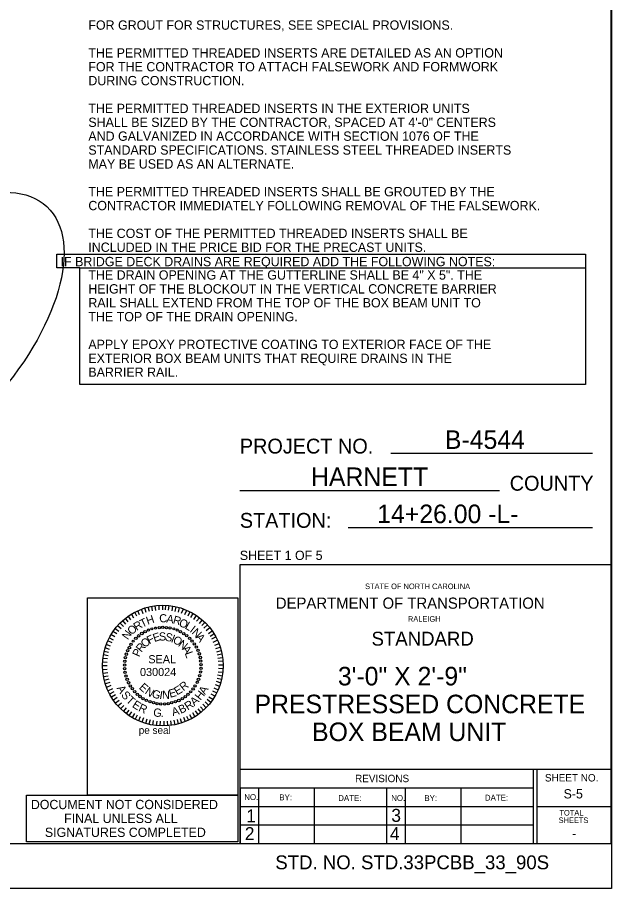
# Model space of a CAD drawing. Extents: x -38 to 94, y -165 to 80.
# Drawn here: x 54.62 to 75.99, y 16.93 to 48.24 of the extents above; entities that cross this region are included whole.
import ezdxf

# ---------------------------------------------------------------- set-up
doc = ezdxf.new("R2010")
doc.units = 0
for name, color, linetype in [('Peseal', 7, 'Continuous'), ('Plan Sheet CELL', 7, 'Continuous'), ('Plot Shape CELL', 7, 'Continuous'), ('Sheet Sticker Exception Certification CELL', 7, 'Continuous'), ('Subtitle Text', 7, 'Continuous'), ('Text', 7, 'Continuous'), ('Title Text', 7, 'Continuous'), ('User Information Notes', 7, 'Continuous'), ('User Information Notes CELL', 7, 'Continuous')]:
    doc.layers.add(name, color=color, linetype=linetype)

msp = doc.modelspace()

# ---------------------------------------------------------------- linework, layer by layer
at = {"layer": 'Peseal'}
for p, q in [((59.14, 26.807), (59.077, 26.964)), ((59.255, 26.849), (59.203, 27.016)), ((59.369, 26.88), (59.328, 27.047)), ((59.484, 26.912), (59.453, 27.079)), ((59.599, 26.922), (59.578, 27.089)), ((59.724, 26.943), (59.714, 27.11)), ((59.849, 26.943), (59.849, 27.11)), ((59.943, 26.943), (59.953, 27.11)), ((60.058, 26.933), (60.079, 27.099)), ((60.183, 26.912), (60.204, 27.079)), ((60.298, 26.891), (60.329, 27.058)), ((60.412, 26.86), (60.454, 27.026)), ((60.527, 26.828), (60.59, 26.985)), ((60.642, 26.776), (60.715, 26.933)), ((58.608, 26.515), (58.504, 26.64)), ((58.702, 26.588), (58.608, 26.724)), ((58.806, 26.651), (58.723, 26.797)), ((58.91, 26.713), (58.837, 26.86)), ((59.015, 26.766), (58.952, 26.912)), ((60.757, 26.724), (60.83, 26.88)), ((60.861, 26.672), (60.944, 26.818)), ((60.965, 26.599), (61.059, 26.745)), ((61.059, 26.536), (61.163, 26.661)), ((58.347, 26.265), (58.222, 26.369)), ((58.431, 26.348), (58.306, 26.474)), ((58.514, 26.432), (58.41, 26.557)), ((61.163, 26.453), (61.268, 26.578)), ((61.247, 26.38), (61.361, 26.494)), ((61.33, 26.286), (61.455, 26.401)), ((61.403, 26.202), (61.539, 26.307)), ((58.128, 25.973), (57.982, 26.056)), ((58.201, 26.077), (58.055, 26.171)), ((58.264, 26.171), (58.139, 26.265)), ((61.487, 26.098), (61.622, 26.192)), ((61.549, 26.004), (61.685, 26.088)), ((57.972, 25.639), (57.815, 25.702)), ((58.024, 25.754), (57.868, 25.827)), ((58.076, 25.858), (57.92, 25.942)), ((61.612, 25.9), (61.758, 25.973)), ((61.664, 25.785), (61.81, 25.858)), ((61.716, 25.671), (61.873, 25.733)), ((57.899, 25.41), (57.742, 25.451)), ((57.93, 25.524), (57.774, 25.577)), ((61.758, 25.556), (61.914, 25.608)), ((61.789, 25.441), (61.946, 25.483)), ((57.847, 25.055), (57.68, 25.066)), ((57.857, 25.18), (57.701, 25.201)), ((57.878, 25.295), (57.711, 25.326)), ((61.81, 25.326), (61.977, 25.358)), ((61.831, 25.212), (61.998, 25.232)), ((61.841, 25.097), (62.008, 25.107)), ((57.847, 24.93), (57.68, 24.93)), ((57.847, 24.805), (57.68, 24.794)), ((61.852, 24.972), (62.019, 24.972)), ((61.852, 24.847), (62.019, 24.836)), ((57.868, 24.68), (57.701, 24.659)), ((57.878, 24.565), (57.721, 24.534)), ((57.909, 24.45), (57.742, 24.409)), ((61.8, 24.492), (61.966, 24.45)), ((61.82, 24.607), (61.987, 24.575)), ((61.841, 24.721), (62.008, 24.701)), ((57.941, 24.336), (57.784, 24.283)), ((57.982, 24.221), (57.826, 24.158)), ((61.685, 24.137), (61.841, 24.075)), ((61.737, 24.263), (61.893, 24.2)), ((61.768, 24.377), (61.935, 24.325)), ((58.034, 24.106), (57.878, 24.033)), ((58.087, 24.002), (57.93, 23.918)), ((58.149, 23.887), (58.003, 23.804)), ((61.507, 23.824), (61.654, 23.731)), ((61.58, 23.929), (61.727, 23.845)), ((61.633, 24.033), (61.789, 23.96)), ((58.212, 23.793), (58.076, 23.699)), ((58.285, 23.689), (58.149, 23.585)), ((58.358, 23.595), (58.243, 23.491)), ((58.452, 23.512), (58.326, 23.386)), ((61.288, 23.553), (61.414, 23.428)), ((61.372, 23.637), (61.497, 23.522)), ((61.445, 23.731), (61.58, 23.626)), ((58.535, 23.428), (58.431, 23.303)), ((58.629, 23.345), (58.535, 23.22)), ((58.723, 23.282), (58.629, 23.147)), ((58.827, 23.22), (58.744, 23.074)), ((60.809, 23.188), (60.892, 23.032)), ((60.913, 23.251), (61.007, 23.105)), ((61.017, 23.313), (61.111, 23.178)), ((61.111, 23.386), (61.215, 23.251)), ((61.205, 23.459), (61.309, 23.345)), ((58.931, 23.157), (58.858, 23.011)), ((59.036, 23.105), (58.973, 22.959)), ((59.15, 23.063), (59.098, 22.907)), ((59.276, 23.021), (59.223, 22.865)), ((59.39, 22.99), (59.349, 22.834)), ((59.505, 22.969), (59.474, 22.802)), ((59.63, 22.948), (59.609, 22.781)), ((59.755, 22.938), (59.745, 22.771)), ((59.88, 22.938), (59.88, 22.771)), ((60.006, 22.948), (60.016, 22.781)), ((60.131, 22.959), (60.152, 22.792)), ((60.245, 22.98), (60.277, 22.813)), ((60.36, 23), (60.402, 22.844)), ((60.475, 23.042), (60.527, 22.875)), ((60.59, 23.084), (60.652, 22.927)), ((60.704, 23.126), (60.777, 22.98))]:
    msp.add_line(p, q, dxfattribs=at)
for centre, radius in [((59.583, 26.291), 0.0369), ((59.719, 26.307), 0.042), ((59.849, 26.317), 0.0417), ((59.98, 26.307), 0.042), ((60.11, 26.296), 0.043), ((58.978, 26.009), 0.0449), ((59.093, 26.093), 0.0449), ((59.213, 26.161), 0.0466), ((59.333, 26.218), 0.0397), ((59.453, 26.26), 0.038), ((60.245, 26.26), 0.038), ((60.365, 26.218), 0.0397), ((60.485, 26.155), 0.042), ((60.6, 26.093), 0.042), ((60.71, 26.015), 0.0407), ((58.707, 25.707), 0.0449), ((58.78, 25.822), 0.0369), ((58.879, 25.921), 0.0442), ((60.814, 25.921), 0.0407), ((60.903, 25.822), 0.0407), ((60.981, 25.723), 0.042), ((58.535, 25.352), 0.0446), ((58.582, 25.478), 0.0397), ((58.645, 25.587), 0.0481), ((61.054, 25.608), 0.042), ((61.116, 25.488), 0.0397), ((61.163, 25.363), 0.0446), ((58.483, 25.092), 0.042), ((58.504, 25.222), 0.043), ((61.195, 25.232), 0.043), ((61.215, 25.102), 0.042), ((58.472, 24.831), 0.042), ((58.472, 24.961), 0.0417), ((58.493, 24.695), 0.042), ((61.205, 24.706), 0.042), ((61.226, 24.972), 0.0417), ((61.226, 24.841), 0.042), ((58.525, 24.565), 0.043), ((58.566, 24.445), 0.0446), ((61.132, 24.445), 0.0446), ((61.174, 24.575), 0.043), ((58.618, 24.325), 0.0466), ((58.676, 24.21), 0.042), ((58.754, 24.111), 0.0407), ((60.939, 24.101), 0.0449), ((61.012, 24.21), 0.042), ((61.085, 24.336), 0.042), ((58.837, 24.002), 0.0442), ((58.931, 23.908), 0.0442), ((59.03, 23.83), 0.0449), ((59.14, 23.757), 0.042), ((60.548, 23.757), 0.042), ((60.657, 23.824), 0.0407), ((60.751, 23.908), 0.0407), ((60.85, 23.997), 0.0407), ((59.26, 23.694), 0.0397), ((59.385, 23.647), 0.0446), ((59.515, 23.605), 0.043), ((59.646, 23.574), 0.042), ((59.776, 23.564), 0.0417), ((59.912, 23.564), 0.0417), ((60.042, 23.574), 0.042), ((60.172, 23.605), 0.043), ((60.303, 23.642), 0.0397), ((60.423, 23.689), 0.0466)]:
    msp.add_circle(centre, radius, dxfattribs=at)
at = {"layer": 'Plan Sheet CELL'}
for p, q in [((75.969, 74.615), (75.969, 18.545)), ((75.302, 32.563), (68.047, 32.563)), ((71.964, 31.228), (62.619, 31.228)), ((75.302, 29.894), (66.518, 29.894)), ((75.969, 28.558), (62.619, 28.558)), ((62.619, 28.558), (62.619, 18.545)), ((62.619, 21.216), (75.969, 21.216)), ((73.166, 21.216), (73.166, 18.545)), ((73.3, 21.216), (73.3, 18.545)), ((62.619, 20.549), (73.171, 20.549)), ((62.628, 20.549), (62.628, 18.545)), ((63.286, 20.549), (63.286, 18.545)), ((65.288, 20.537), (65.288, 18.535)), ((67.894, 20.549), (67.894, 18.528)), ((68.563, 20.549), (68.563, 18.543)), ((70.565, 20.549), (70.565, 18.543)), ((62.619, 19.88), (73.193, 19.88)), ((73.3, 19.88), (75.946, 19.88)), ((62.619, 19.213), (73.171, 19.213)), ((-9.472, 18.545), (75.969, 18.545)), ((75.992, 16.927), (75.992, 16.927))]:
    msp.add_line(p, q, dxfattribs=at)
at = {"layer": 'Plot Shape CELL'}
msp.add_lwpolyline([(-12.286, 75.667), (75.992, 75.667), (75.992, 16.927), (-12.286, 16.927)], close=True, dxfattribs=at)
at = {"layer": 'Sheet Sticker Exception Certification CELL'}
msp.add_lwpolyline([(54.947, 20.286), (62.553, 20.286), (62.553, 18.612), (54.947, 18.612)], close=True, dxfattribs=at)
at = {"layer": 'User Information Notes'}
for p, q in [((56.862, 39.237), (75.059, 39.237)), ((59.849, 24.94), (59.849, 24.94))]:
    msp.add_line(p, q, dxfattribs=at)
msp.add_lwpolyline([(56.862, 39.237), (56.041, 39.237), (56.041, 39.735), (75.059, 39.735), (75.059, 35.039), (56.862, 35.039)], close=True, dxfattribs=at)
msp.add_ellipse((51.167, 36.612), major_axis=(4.509, 4.826), ratio=0.506929, dxfattribs=at)
at = {"layer": 'User Information Notes CELL'}
msp.add_line((59.849, 24.94), (59.849, 24.94), dxfattribs=at)
msp.add_lwpolyline([(57.146, 27.377), (62.553, 27.377), (62.553, 20.286), (57.146, 20.286)], close=True, dxfattribs=at)
msp.add_circle((59.849, 24.94), 2.169, dxfattribs=at)

# ---------------------------------------------------------------- texts
at = {"layer": 'Peseal'}
for s, height, rotation, p in [('T', 0.292, 25.943, (59.109, 26.296)), ('H', 0.292, 18.9162, (59.307, 26.401)), ('C', 0.292, 4.8625, (59.734, 26.484)), ('A', 0.292, 350.8088, (59.964, 26.494)), ('R', 0.292, 343.7819, (60.193, 26.463)), ('O', 0.292, 336.7551, (60.402, 26.38)), ('O', 0.292, 39.9967, (58.723, 26.025)), ('R', 0.292, 32.9699, (58.91, 26.182)), ('L', 0.292, 329.7282, (60.621, 26.286)), ('I', 0.292, 322.7014, (60.798, 26.171)), ('N', 0.292, 54.0504, (58.587, 25.848)), ('F', 0.292, 26.4777, (59.359, 25.702)), ('E', 0.292, 18.4448, (59.547, 25.785)), ('S', 0.292, 2.3789, (59.714, 25.837)), ('S', 0.292, 346.313, (59.912, 25.848)), ('I', 0.292, 338.28, (60.12, 25.796)), ('O', 0.292, 330.2471, (60.183, 25.785)), ('N', 0.292, 315.6745, (60.871, 26.109)), ('A', 0.292, 308.6477, (61.017, 25.952)), ('R', 0.292, 50.5765, (59.077, 25.399)), ('O', 0.292, 42.5436, (59.213, 25.566)), ('N', 0.292, 322.2141, (60.381, 25.66)), ('P', 0.292, 66.6424, (59.004, 25.232)), ('A', 0.292, 306.1483, (60.527, 25.535)), ('L', 0.292, 290.0824, (60.631, 25.389)), ('A', 0.296, 300.3993, (58.181, 24.131)), ('E', 0.292, 318.5179, (58.973, 24.127)), ('N', 0.292, 326.5361, (59.182, 23.95)), ('E', 0.292, 14.6452, (60.11, 23.783)), ('E', 0.292, 30.6815, (60.36, 23.866)), ('R', 0.292, 38.6997, (60.59, 24.012)), ('A', 0.296, 59.6007, (61.37, 23.879)), ('S', 0.296, 309.4349, (58.329, 23.879)), ('T', 0.296, 318.1096, (58.506, 23.662)), ('G', 0.292, 342.5725, (59.432, 23.814)), ('I', 0.292, 350.5906, (59.714, 23.751)), ('N', 0.292, 358.6088, (59.818, 23.751)), ('A', 0.296, 42.3241, (60.986, 23.476)), ('H', 0.296, 51.3597, (61.202, 23.672)), ('E', 0.296, 327.1453, (58.724, 23.467)), ('R', 0.296, 335.458, (58.949, 23.32)), ('B', 0.296, 24.8312, (60.493, 23.202)), ('R', 0.296, 33.5776, (60.75, 23.32)), ('G', 0.296, 353.3858, (59.491, 23.121)), ('A', 0.296, 15.7955, (60.212, 23.122)), ('.', 0.296, 2.1323, (59.772, 23.088))]:
    msp.add_text(s, height=height, rotation=rotation, dxfattribs=at).set_placement(p)
for s, p in [('SEAL', (59.328, 25.024)), ('030024', (59.028, 24.565))]:
    msp.add_text(s, height=0.2921, dxfattribs=at).set_placement(p)
at = {"layer": 'Plan Sheet CELL'}
for s, height, p in [('PROJECT NO.', 0.534, (62.619, 32.563)), ('COUNTY', 0.534, (72.328, 31.228)), ('STATION:', 0.534, (62.619, 29.894)), ('SHEET 1 OF 5 ', 0.33375, (62.619, 28.737)), ('STATE OF NORTH CAROLINA', 0.20024, (67.124, 27.69)), ('DEPARTMENT OF TRANSPORTATION', 0.40049, (63.914, 26.986)), ('RALEIGH', 0.2002, (68.666, 26.518)), ('REVISIONS', 0.267, (66.765, 20.751)), ('SHEET NO.', 0.267, (73.594, 20.776)), ('NO.', 0.2128, (62.778, 20.109)), ('BY:', 0.2128, (64.038, 20.099)), ('DATE:', 0.2128, (66.159, 20.075)), ('NO.', 0.2128, (68.064, 20.075)), ('BY:', 0.2128, (69.257, 20.074)), ('DATE:', 0.2128, (71.434, 20.087)), ('1', 0.467, (62.848, 19.304)), ('3', 0.467, (68.069, 19.325)), ('TOTAL', 0.2002, (74.117, 19.552)), ('SHEETS', 0.2002, (74.086, 19.282)), ('2', 0.467, (62.799, 18.668)), ('4', 0.467, (68.02, 18.668))]:
    msp.add_text(s, height=height, dxfattribs=at).set_placement(p)
at = {"layer": 'Sheet Sticker Exception Certification CELL'}
for s, p in [('DOCUMENT NOT CONSIDERED', (55.103, 19.782)), ('FINAL UNLESS ALL', (56.3, 19.283)), ('SIGNATURES COMPLETED', (55.607, 18.783))]:
    msp.add_text(s, height=0.333, dxfattribs=at).set_placement(p)
at = {"layer": 'Subtitle Text'}
for s, height, p in [('STANDARD', 0.5, (67.357, 25.659)), ('3\'-0" X 2\'-9"', 0.667, (66.147, 24.229)), ('PRESTRESSED CONCRETE', 0.667, (63.149, 23.228)), ('BOX BEAM UNIT', 0.667, (65.218, 22.228))]:
    msp.add_text(s, height=height, dxfattribs=at).set_placement(p)
at = {"layer": 'Text'}
for s, height, p in [('FOR GROUT FOR STRUCTURES, SEE SPECIAL PROVISIONS. ', 0.33455, (57.17, 47.796)), ('THE PERMITTED THREADED INSERTS ARE DETAILED AS AN OPTION ', 0.33455, (57.17, 46.798)), ('FOR THE CONTRACTOR TO ATTACH FALSEWORK AND FORMWORK ', 0.33455, (57.17, 46.299)), ('DURING CONSTRUCTION.', 0.33455, (57.17, 45.8)), ('THE PERMITTED THREADED INSERTS IN THE EXTERIOR UNITS ', 0.33455, (57.17, 44.802)), ('SHALL BE SIZED BY THE CONTRACTOR, SPACED AT 4\'-0" CENTERS ', 0.33455, (57.17, 44.303)), ('AND GALVANIZED IN ACCORDANCE WITH SECTION 1076 OF THE', 0.33455, (57.17, 43.804)), ('STANDARD SPECIFICATIONS. STAINLESS STEEL THREADED INSERTS ', 0.33455, (57.17, 43.305)), ('MAY BE USED AS AN ALTERNATE.', 0.33455, (57.17, 42.806)), ('THE PERMITTED THREADED INSERTS SHALL BE GROUTED BY THE', 0.33455, (57.17, 41.808)), ('CONTRACTOR IMMEDIATELY FOLLOWING REMOVAL OF THE FALSEWORK.', 0.33455, (57.17, 41.309)), ('THE COST OF THE PERMITTED THREADED INSERTS SHALL BE ', 0.33455, (57.17, 40.311)), ('INCLUDED IN THE PRICE BID FOR THE PRECAST UNITS.', 0.33455, (57.17, 39.812)), ('S-5', 0.333, (74.266, 20.167)), ('-', 0.333, (74.573, 18.744)), ('STD. NO. STD.33PCBB_33_90S', 0.5, (63.896, 17.62))]:
    msp.add_text(s, height=height, dxfattribs=at).set_placement(p)
at = {"layer": 'Title Text'}
for s, p in [('B-4544', (69.997, 32.73)), ('HARNETT', (65.181, 31.395)), ('14+26.00 -L-', (67.562, 30.061))]:
    msp.add_text(s, height=0.667, dxfattribs=at).set_placement(p)
at = {"layer": 'User Information Notes'}
for s, p in [('IF BRIDGE DECK DRAINS ARE REQUIRED ADD THE FOLLOWING NOTES:', (56.172, 39.296)), ('THE DRAIN OPENING AT THE GUTTERLINE SHALL BE 4" X 5". THE ', (57.17, 38.814)), ('HEIGHT OF THE BLOCKOUT IN THE VERTICAL CONCRETE BARRIER ', (57.17, 38.315)), ('RAIL SHALL EXTEND FROM THE TOP OF THE BOX BEAM UNIT TO ', (57.17, 37.816)), ('THE TOP OF THE DRAIN OPENING. ', (57.17, 37.317)), ('APPLY EPOXY PROTECTIVE COATING TO EXTERIOR FACE OF THE ', (57.17, 36.319)), ('EXTERIOR BOX BEAM UNITS THAT REQUIRE DRAINS IN THE ', (57.17, 35.82)), ('BARRIER RAIL. ', (57.17, 35.321))]:
    msp.add_text(s, height=0.33455, dxfattribs=at).set_placement(p)
at = {"layer": 'User Information Notes CELL'}
msp.add_text('pe seal', height=0.267, dxfattribs=at).set_placement((58.984, 22.486))

doc.saveas('drawing.dxf')
